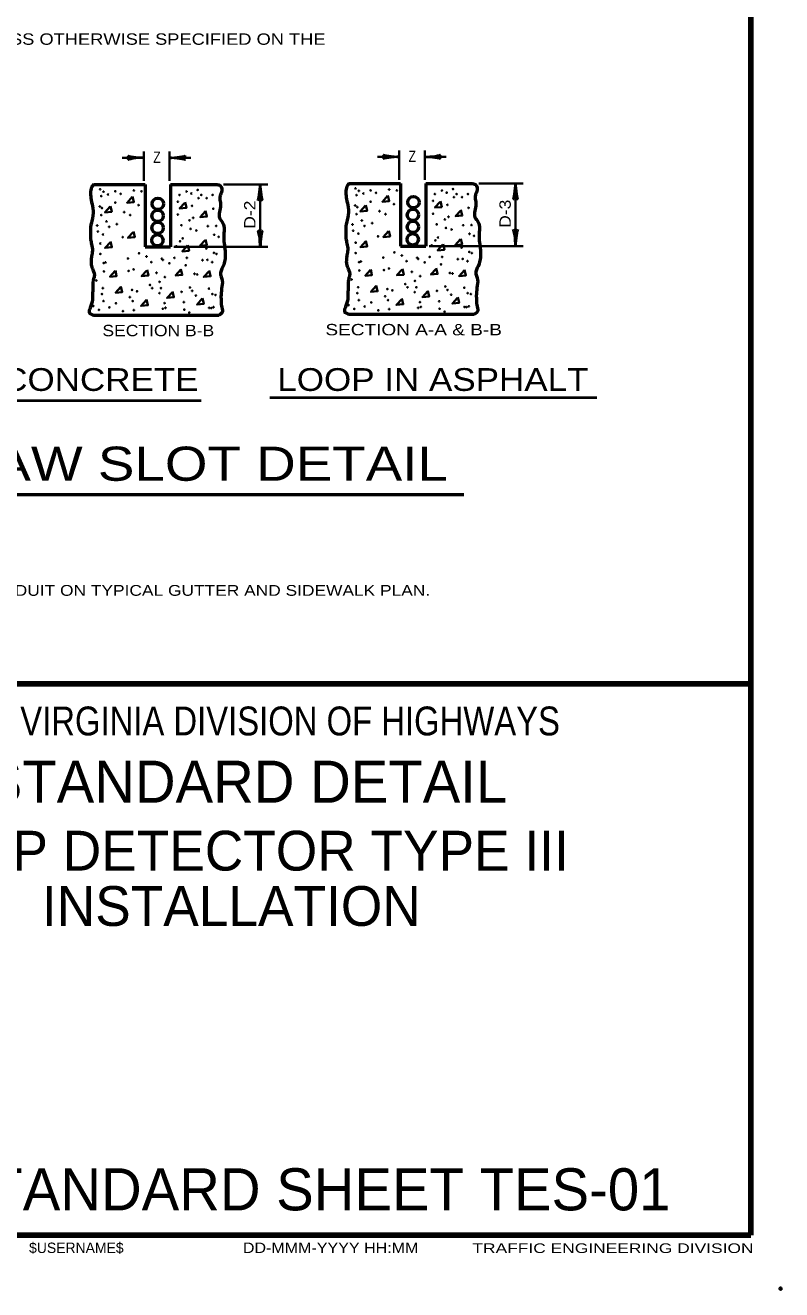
# Model space of a CAD drawing. Extents: x -90 to 623, y -379 to 75.
# Drawn here: x 489.7 to 622.6, y -378.6 to -156.3 of the extents above; entities that cross this region are included whole.
import ezdxf
from ezdxf.enums import TextEntityAlignment as Align

# ---------------------------------------------------------------- set-up
doc = ezdxf.new("R2010")
doc.units = 0
doc.header["$LTSCALE"] = 0.8
doc.header["$PDMODE"] = 32
doc.header["$PDSIZE"] = 0.4
doc.layers.add('1', color=7, linetype='Continuous', lineweight=35)
doc.layers.add('61', color=7, linetype='Continuous', lineweight=35)

msp = doc.modelspace()

# ---------------------------------------------------------------- linework, layer by layer
at = {"layer": '1', "lineweight": 158}
for q in [(617.1938, 69.4188), (617.1938, -272.0812), (-42.4728, -368.9978)]:
    msp.add_line((617.1938, -368.9978), q, dxfattribs=at)
at = {"layer": '1', "lineweight": 13}
msp.add_line((617.1938, -368.9978), (617.1938, 69.4188), dxfattribs=at)
at = {"layer": '1'}
for p, q in [((506.7147, -179.6138), (510.5347, -179.6138)), ((510.5427, -183.6718), (510.5427, -178.4999)), ((514.9897, -179.6138), (518.8097, -179.6138)), ((515.0427, -183.6718), (515.0427, -178.4999)), ((551.5907, -179.4547), (555.4108, -179.4547)), ((555.4188, -183.5127), (555.4188, -178.3408)), ((559.8657, -179.4547), (563.6857, -179.4547)), ((559.9188, -183.5127), (559.9188, -178.3408)), ((524.5377, -184.3083), (532.3499, -184.3083)), ((530.9827, -184.2287), (530.9827, -195.2898)), ((569.4138, -184.1492), (577.226, -184.1492)), ((575.8587, -184.0697), (575.8587, -195.1308)), ((515.7853, -195.2887), (532.3499, -195.2887)), ((560.6614, -195.1296), (577.226, -195.1296))]:
    msp.add_line(p, q, dxfattribs=at)
at = {"layer": '1', "lineweight": 53}
for p, q in [((501.7418, -184.2891), (510.7418, -184.2891)), ((510.7418, -184.2891), (510.7418, -195.2891)), ((515.2418, -184.2891), (523.2418, -184.2891)), ((515.2418, -184.2891), (515.2418, -195.2891)), ((546.6179, -184.13), (555.6179, -184.13)), ((555.6179, -184.13), (555.6179, -195.13)), ((560.1179, -184.13), (568.1179, -184.13)), ((560.1179, -184.13), (560.1179, -195.13)), ((510.7418, -195.2891), (515.2418, -195.2891)), ((555.6179, -195.13), (560.1179, -195.13)), ((501.7418, -207.2891), (523.7418, -207.2891)), ((546.6179, -207.13), (568.6179, -207.13)), ((475.4047, -238.811), (566.749, -238.811))]:
    msp.add_line(p, q, dxfattribs=at)
at = {"layer": '1', "lineweight": 40}
for p, q in [((457.8999, -222.2609), (520.5994, -222.2609)), ((532.6935, -221.7835), (590.1417, -221.7835))]:
    msp.add_line(p, q, dxfattribs=at)
at = {"layer": '1'}
for points in [[(508.5107, -186.4747), (507.5894, -187.5112), (508.7794, -187.396), (508.5491, -186.3979)], [(553.3868, -186.3156), (552.4655, -187.3521), (553.6555, -187.2369), (553.4252, -186.2388)], [(504.612, -188.1854), (503.6907, -189.2219), (504.8807, -189.1068), (504.6503, -188.1087)], [(517.7406, -187.5091), (516.8193, -188.5456), (518.0092, -188.4304), (517.7789, -187.4323)], [(521.3609, -189.0208), (520.4396, -190.0573), (521.6296, -189.9422), (521.3992, -188.9441)], [(549.4881, -188.0263), (548.5667, -189.0628), (549.7568, -188.9477), (549.5264, -187.9496)], [(562.6167, -187.35), (561.6953, -188.3865), (562.8853, -188.2713), (562.655, -187.2732)], [(566.237, -188.8618), (565.3157, -189.8982), (566.5057, -189.7831), (566.2753, -188.785)], [(508.6699, -192.6809), (507.7486, -193.7174), (508.9386, -193.6022), (508.7082, -192.6042)], [(553.546, -192.5218), (552.6247, -193.5583), (553.8147, -193.4432), (553.5843, -192.4451)], [(504.6517, -194.4314), (503.7304, -195.4679), (504.9204, -195.3527), (504.6901, -194.3547)], [(518.218, -195.0282), (517.2967, -196.0647), (518.4867, -195.9495), (518.2563, -194.9514)], [(521.3212, -194.0734), (520.3998, -195.1099), (521.5898, -194.9947), (521.3595, -193.9967)], [(549.5278, -194.2723), (548.6065, -195.3088), (549.7965, -195.1937), (549.5662, -194.1956)], [(563.0941, -194.8691), (562.1727, -195.9056), (563.3628, -195.7904), (563.1324, -194.7923)], [(566.1972, -193.9143), (565.2759, -194.9508), (566.4659, -194.8357), (566.2356, -193.8376)], [(505.4872, -199.484), (504.5658, -200.5205), (505.7558, -200.4053), (505.5255, -199.4073)], [(511.0569, -199.4044), (510.1356, -200.4409), (511.3256, -200.3257), (511.0952, -199.3277)], [(517.0245, -199.2851), (516.1032, -200.3216), (517.2932, -200.2064), (517.0628, -199.2083)], [(521.9974, -199.5238), (521.0761, -200.5602), (522.2661, -200.4451), (522.0358, -199.447)], [(550.3632, -199.3249), (549.4419, -200.3614), (550.6319, -200.2463), (550.4016, -199.2482)], [(555.933, -199.2453), (555.0117, -200.2818), (556.2017, -200.1667), (555.9713, -199.1686)], [(561.9006, -199.126), (560.9792, -200.1625), (562.1693, -200.0473), (561.9389, -199.0493)], [(566.8735, -199.3647), (565.9522, -200.4012), (567.1422, -200.286), (566.9118, -199.2879)], [(506.4818, -202.3086), (505.5605, -203.3451), (506.7505, -203.2299), (506.5202, -202.2318)], [(551.3579, -202.1495), (550.4366, -203.186), (551.6266, -203.0708), (551.3963, -202.0727)], [(515.5525, -203.2237), (514.6312, -204.2602), (515.8212, -204.145), (515.5908, -203.1469)], [(520.8039, -204.3773), (519.8826, -205.4138), (521.0726, -205.2987), (520.8423, -204.3006)], [(555.8534, -204.457), (554.9321, -205.4935), (556.1221, -205.3783), (555.8918, -204.3802)], [(560.4286, -203.0646), (559.5072, -204.1011), (560.6972, -203.9859), (560.4669, -202.9878)], [(565.68, -204.2182), (564.7587, -205.2548), (565.9487, -205.1396), (565.7183, -204.1415)], [(510.9773, -204.6161), (510.056, -205.6526), (511.246, -205.5374), (511.0157, -204.5393)]]:
    msp.add_lwpolyline(points, dxfattribs=at)
at = {"layer": '1', "lineweight": 158}
msp.add_lwpolyline([(435.5272, -368.9978), (435.5272, -272.0812), (617.1938, -272.0812)], dxfattribs=at)
at = {"layer": '1'}
for centre in [(502.8498, -185.1522), (503.0487, -186.3457), (503.4466, -185.5897), (504.2422, -186.0672), (505.5153, -185.5102), (506.4701, -185.9478), (508.7776, -185.3511), (510.1302, -185.5102), (516.8139, -186.1467), (518.0472, -185.55), (518.8827, -185.9081), (519.9966, -185.2715), (520.1558, -186.7037), (520.6332, -186.1467), (521.5879, -186.7037), (522.6223, -186.1467), (547.7259, -184.9931), (547.9248, -186.1866), (548.3227, -185.4307), (549.1183, -185.9081), (550.3914, -185.3512), (551.3462, -185.7887), (553.6537, -185.192), (555.0063, -185.3512), (561.69, -185.9877), (562.9232, -185.3909), (563.7587, -185.749), (564.8727, -185.1124), (565.0318, -186.5447), (565.5092, -185.9877), (566.464, -186.5447), (567.4984, -185.9877), (502.81, -188.1757), (503.1681, -188.4543), (505.5153, -187.4994), (509.613, -187.937), (516.4956, -187.3402), (519.002, -188.0563), (522.7417, -188.5736), (547.6861, -188.0167), (548.0442, -188.2952), (550.3914, -187.3403), (554.4891, -187.7779), (561.3717, -187.1812), (563.8781, -187.8972), (567.6178, -188.4145), (503.0487, -189.6875), (503.9638, -190.8014), (507.0669, -189.1703), (508.141, -189.6875), (516.4956, -189.6079), (518.5643, -190.6025), (519.2009, -190.1649), (547.9248, -189.5284), (548.8398, -190.6423), (550.6699, -191.1197), (551.943, -189.0112), (553.0171, -189.5284), (561.3717, -189.4488), (563.4404, -190.4434), (564.077, -190.0058), (502.3326, -191.5176), (502.452, -192.5917), (503.367, -193.1089), (504.4412, -191.7562), (505.7938, -191.2788), (517.1322, -191.4777), (518.7633, -192.1143), (519.7579, -192.3928), (521.7868, -191.6369), (522.9008, -193.1487), (523.2588, -191.5972), (547.2087, -191.3585), (547.3281, -192.4327), (548.2431, -192.9498), (549.3172, -191.5972), (551.7043, -193.4272), (562.0082, -191.3187), (563.6394, -191.9553), (564.634, -192.2337), (566.6629, -191.4778), (567.7769, -192.9896), (568.1349, -191.4381), (568.5726, -193.3477), (502.8896, -194.7002), (506.8282, -193.5863), (516.2569, -195.1777), (516.8934, -194.3024), (517.3708, -193.7852), (521.5083, -195.5755), (523.6965, -193.5067), (547.7657, -194.5412), (561.133, -195.0186), (561.7695, -194.1433), (562.2469, -193.6262), (566.3844, -195.4164), (502.8896, -196.5303), (507.7432, -197.326), (509.6926, -196.4109), (511.0055, -196.9679), (513.7107, -197.3657), (513.8699, -197.5647), (515.8988, -197.2067), (518.087, -197.2067), (520.8321, -197.6045), (521.7072, -197.5647), (522.861, -196.3314), (523.2987, -196.5303), (547.7657, -196.3713), (548.6807, -197.8432), (552.6192, -197.1669), (554.5687, -196.2518), (555.8816, -196.8088), (556.717, -197.8034), (558.5868, -197.2067), (558.746, -197.4056), (560.7749, -197.0476), (562.9631, -197.0476), (565.7082, -197.4454), (566.5833, -197.4056), (567.4188, -197.8034), (567.7371, -196.1723), (568.1748, -196.3713), (503.4863, -198.1217), (503.5261, -199.5937), (503.8046, -198.0023), (507.8626, -199.5141), (508.7378, -199.2356), (511.8409, -197.9625), (512.7559, -199.8323), (515.0236, -198.1614), (517.8881, -198.5195), (519.4396, -200.0312), (519.917, -200.1108), (522.5427, -197.9625), (548.3624, -197.9626), (548.4022, -199.4346), (552.7387, -199.355), (553.6139, -199.0765), (557.632, -199.6732), (559.8997, -198.0023), (562.7642, -198.3604), (564.3157, -199.8722), (564.7931, -199.9518), (502.1735, -201.185), (511.6022, -201.9807), (513.3129, -201.4237), (514.2279, -200.5882), (547.0496, -201.0259), (556.4783, -201.8216), (558.189, -201.2646), (559.104, -200.4292), (563.52, -202.2592), (503.1681, -203.572), (503.3272, -202.5377), (508.0615, -204.129), (508.4593, -202.8559), (509.3346, -203.0946), (512.0001, -202.5377), (513.2732, -203.4129), (513.5516, -202.5377), (517.1719, -203.1742), (518.6439, -202.4183), (519.0417, -203.0151), (519.6783, -203.8505), (521.9857, -202.6172), (522.5825, -203.572), (523.1395, -203.7312), (548.0442, -203.4129), (548.2033, -202.3786), (552.9376, -203.9699), (553.3354, -202.6968), (554.2107, -202.9355), (556.8762, -202.3786), (558.1492, -203.2538), (558.4277, -202.3786), (562.048, -203.0151), (563.9178, -202.856), (564.5544, -203.6914), (566.8618, -202.4582), (567.4586, -203.4129), (568.0156, -203.5721), (501.6562, -205.6806), (502.6509, -206.3569), (503.4466, -204.8053), (504.4809, -205.9193), (505.6347, -205.2032), (506.8679, -206.5956), (508.5787, -204.8053), (508.7776, -206.3967), (513.8699, -206.158), (514.1882, -205.1634), (514.3473, -205.9988), (517.5697, -205.0042), (517.6493, -206.3171), (522.0256, -205.9988), (522.3836, -206.0386), (522.7814, -205.8795), (546.5323, -205.5215), (547.527, -206.1978), (548.3227, -204.6462), (549.357, -205.7602), (550.5108, -205.0441), (551.744, -206.4365), (553.4547, -204.6462), (553.6537, -206.2376), (558.746, -205.9989), (559.0643, -205.0043), (559.2234, -205.8397), (562.4458, -204.8452), (562.5254, -206.158), (563.4007, -206.6753), (566.9017, -205.8397), (567.2597, -205.8795), (567.6575, -205.7204), (518.5246, -206.8343)]:
    msp.add_circle(centre, 0.0607, dxfattribs=at)
at = {"layer": '1', "lineweight": 53}
for centre in [(513.0005, -187.7103), (557.9164, -187.4319), (512.9607, -189.8189), (557.8368, -189.6598), (512.9607, -191.9274), (557.8368, -191.7683), (512.921, -194.1155), (557.7971, -193.9564)]:
    msp.add_circle(centre, 1, dxfattribs=at)
at = {"layer": '1', "lineweight": 40}
for centre, major_axis, ratio, start_param, end_param in [((509.4435, -179.8901), (1.7857, 0.1562), 0.122415, 0.89635335, 3.14159265), ((509.4142, -179.4022), (1.7565, -0.1757), 0.07063, 3.14071475, 5.41810995), ((516.1102, -179.8254), (1.7565, -0.1757), 0.07063, 6.28230741, 8.55970261), ((516.0809, -179.3375), (-1.7857, -0.1562), 0.122415, 0.89635335, 3.14159265), ((554.3196, -179.731), (1.7857, 0.1562), 0.122415, 0.89635335, 3.14159265), ((554.2902, -179.2431), (1.7565, -0.1757), 0.07063, 3.14071475, 5.41810995), ((560.9863, -179.6664), (1.7565, -0.1757), 0.07063, 6.28230741, 8.55970261), ((560.9569, -179.1785), (-1.7857, -0.1562), 0.122415, 0.89635335, 3.14159265), ((530.7711, -185.3493), (-0.1757, -1.7565), 0.07063, 6.28230741, 8.55970261), ((531.259, -185.3199), (-0.1562, 1.7857), 0.122415, 0.89635335, 3.14159265), ((575.6471, -185.1902), (-0.1757, -1.7565), 0.07063, 6.28230741, 8.55970261), ((576.135, -185.1609), (-0.1562, 1.7857), 0.122415, 0.89635335, 3.14159265), ((530.7064, -194.1986), (0.1562, -1.7857), 0.122415, 0.89635335, 3.14159265), ((531.1943, -194.1693), (0.1757, 1.7565), 0.07063, 6.28230741, 8.55970261), ((575.5825, -194.0396), (0.1562, -1.7857), 0.122415, 0.89635335, 3.14159265), ((576.0704, -194.0102), (0.1757, 1.7565), 0.07063, 6.28230741, 8.55970261)]:
    msp.add_ellipse(centre, major_axis=major_axis, ratio=ratio, start_param=start_param, end_param=end_param, dxfattribs=at)
at = {"layer": '1', "lineweight": 53}
for points in [[(501.7418, -184.2891), (501.3439, -184.8061), (501.1848, -185.8404), (501.2643, -187.0339), (501.5826, -188.4662), (501.5031, -190.2962), (501.1848, -191.808), (501.1848, -192.365), (501.1848, -193.9563), (501.3439, -194.8316), (501.5031, -195.9455), (501.3439, -196.9003), (501.2643, -197.7756), (501.2643, -198.4121), (501.5826, -199.2873), (501.8213, -200.4808), (501.6622, -201.0378), (501.5826, -201.6743), (501.5826, -202.6292), (501.5031, -203.5044), (501.5031, -204.6183), (501.1052, -205.971), (500.9461, -206.8462), (501.7418, -207.2891)], [(523.2418, -184.2891), (523.9411, -184.4878), (524.1798, -185.6813), (523.9411, -186.2382), (524.0206, -187.9092), (523.8615, -190.2167), (524.4184, -191.0919), (524.5776, -193.3993), (524.6572, -194.6724), (524.8162, -197.2982), (524.4184, -198.8099), (524.0206, -200.1626), (524.2593, -200.8787), (524.2593, -202.2313), (524.1002, -203.7431), (524.1002, -204.6183), (524.1798, -205.6527), (524.3389, -206.6871), (523.7418, -207.2891)], [(546.6179, -184.13), (546.22, -184.647), (546.0608, -185.6813), (546.1404, -186.8748), (546.4587, -188.3071), (546.3792, -190.1372), (546.0608, -191.6489), (546.0608, -192.2059), (546.0608, -193.7972), (546.22, -194.6725), (546.3792, -195.7864), (546.22, -196.7412), (546.1404, -197.6165), (546.1404, -198.253), (546.4587, -199.1282), (546.6974, -200.3217), (546.5382, -200.8787), (546.4587, -201.5152), (546.4587, -202.4701), (546.3792, -203.3453), (546.3792, -204.4592), (545.9812, -205.8119), (545.8222, -206.6872), (546.6179, -207.13)], [(568.1179, -184.13), (568.8172, -184.3287), (569.0558, -185.5222), (568.8172, -186.0792), (568.8967, -187.7501), (568.7376, -190.0576), (569.2945, -190.9328), (569.4537, -193.2403), (569.5332, -194.5133), (569.6923, -197.1391), (569.2945, -198.6508), (568.8967, -200.0035), (569.1354, -200.7196), (569.1354, -202.0722), (568.9762, -203.584), (568.9762, -204.4592), (569.0558, -205.4937), (569.215, -206.528), (568.6179, -207.13)]]:
    msp.add_spline(points, degree=3, dxfattribs=at)
at = {"layer": '1'}
msp.add_point((622.4438, -378.4145), dxfattribs=at)
at = {"layer": '61', "lineweight": 53}
for q in [(489.9438, -368.9978), (489.9438, -368.9978), (489.9438, -368.9978), (490.1938, -368.9978), (490.1938, -368.9978)]:
    msp.add_line((617.1938, -368.9978), q, dxfattribs=at)

# ---------------------------------------------------------------- texts
at = {"layer": '1'}
for s, height, width, p in [('THE "X" DIMENSION SHALL BE 6 FOOT UNLESS OTHERWISE SPECIFIED ON THE', 2, 1.2, (418.0359, -159.7507)), ('REMOVE SIGN ON TYPE R CONDUIT ON TYPICAL GUTTER AND SIDEWALK PLAN.', 1.9, 1.2, (441.4286, -256.6228)), ('DD-MMM-YYYY HH:MM', 1.833, 1.15, (527.9438, -372.1645)), ('TRAFFIC ENGINEERING DIVISION', 1.693, 1.35, (568.2772, -372.1645))]:
    msp.add_text(s, height=height, dxfattribs=dict(at, width=width)).set_placement(p)
for s, height, width, p in [('Z', 2, 0.8, (512.8413, -180.5142)), ('Z', 2, 0.8, (557.7174, -180.3551)), ('SECTION A-A & B-B', 2, 1.25, (557.9562, -210.8294)), ('SECTION B-B', 2, 1.15, (513.0801, -210.9885)), ('LOOP IN CONCRETE', 4, 1.15, (489.5678, -220.6008)), ('LOOP IN ASPHALT', 4, 1.15, (561.338, -220.6008)), ('SAW SLOT DETAIL', 6, 1.2, (520.9174, -236.4004)), ('WEST VIRGINIA DIVISION OF HIGHWAYS', 5.074, 0.85, (527.1105, -281.1645))]:
    msp.add_text(s, height=height, dxfattribs=dict(at, width=width)).set_placement(p, align=Align.CENTER)
at = {"layer": '1', "width": 1.15}
for s, p in [('D-2', (530.1527, -189.6192)), ('D-3', (575.0288, -189.4601))]:
    msp.add_text(s, height=2, rotation=90, dxfattribs=at).set_placement(p, align=Align.CENTER)
at = {"layer": '1'}
for s, height, p in [('STANDARD DETAIL', 7.401, (528.4855, -292.9978)), ('LOOP DETECTOR TYPE III', 7, (526.4484, -304.9311)), ('INSTALLATION', 7, (525.9161, -314.6579))]:
    msp.add_text(s, height=height, dxfattribs=at).set_placement(p, align=Align.CENTER)
for s, height, p in [('STANDARD SHEET TES-01', 7.401, (476.6105, -364.6645)), ('$USERNAME$', 1.833, (490.3605, -372.1645))]:
    msp.add_text(s, height=height, dxfattribs=at).set_placement(p)

doc.saveas('drawing.dxf')
